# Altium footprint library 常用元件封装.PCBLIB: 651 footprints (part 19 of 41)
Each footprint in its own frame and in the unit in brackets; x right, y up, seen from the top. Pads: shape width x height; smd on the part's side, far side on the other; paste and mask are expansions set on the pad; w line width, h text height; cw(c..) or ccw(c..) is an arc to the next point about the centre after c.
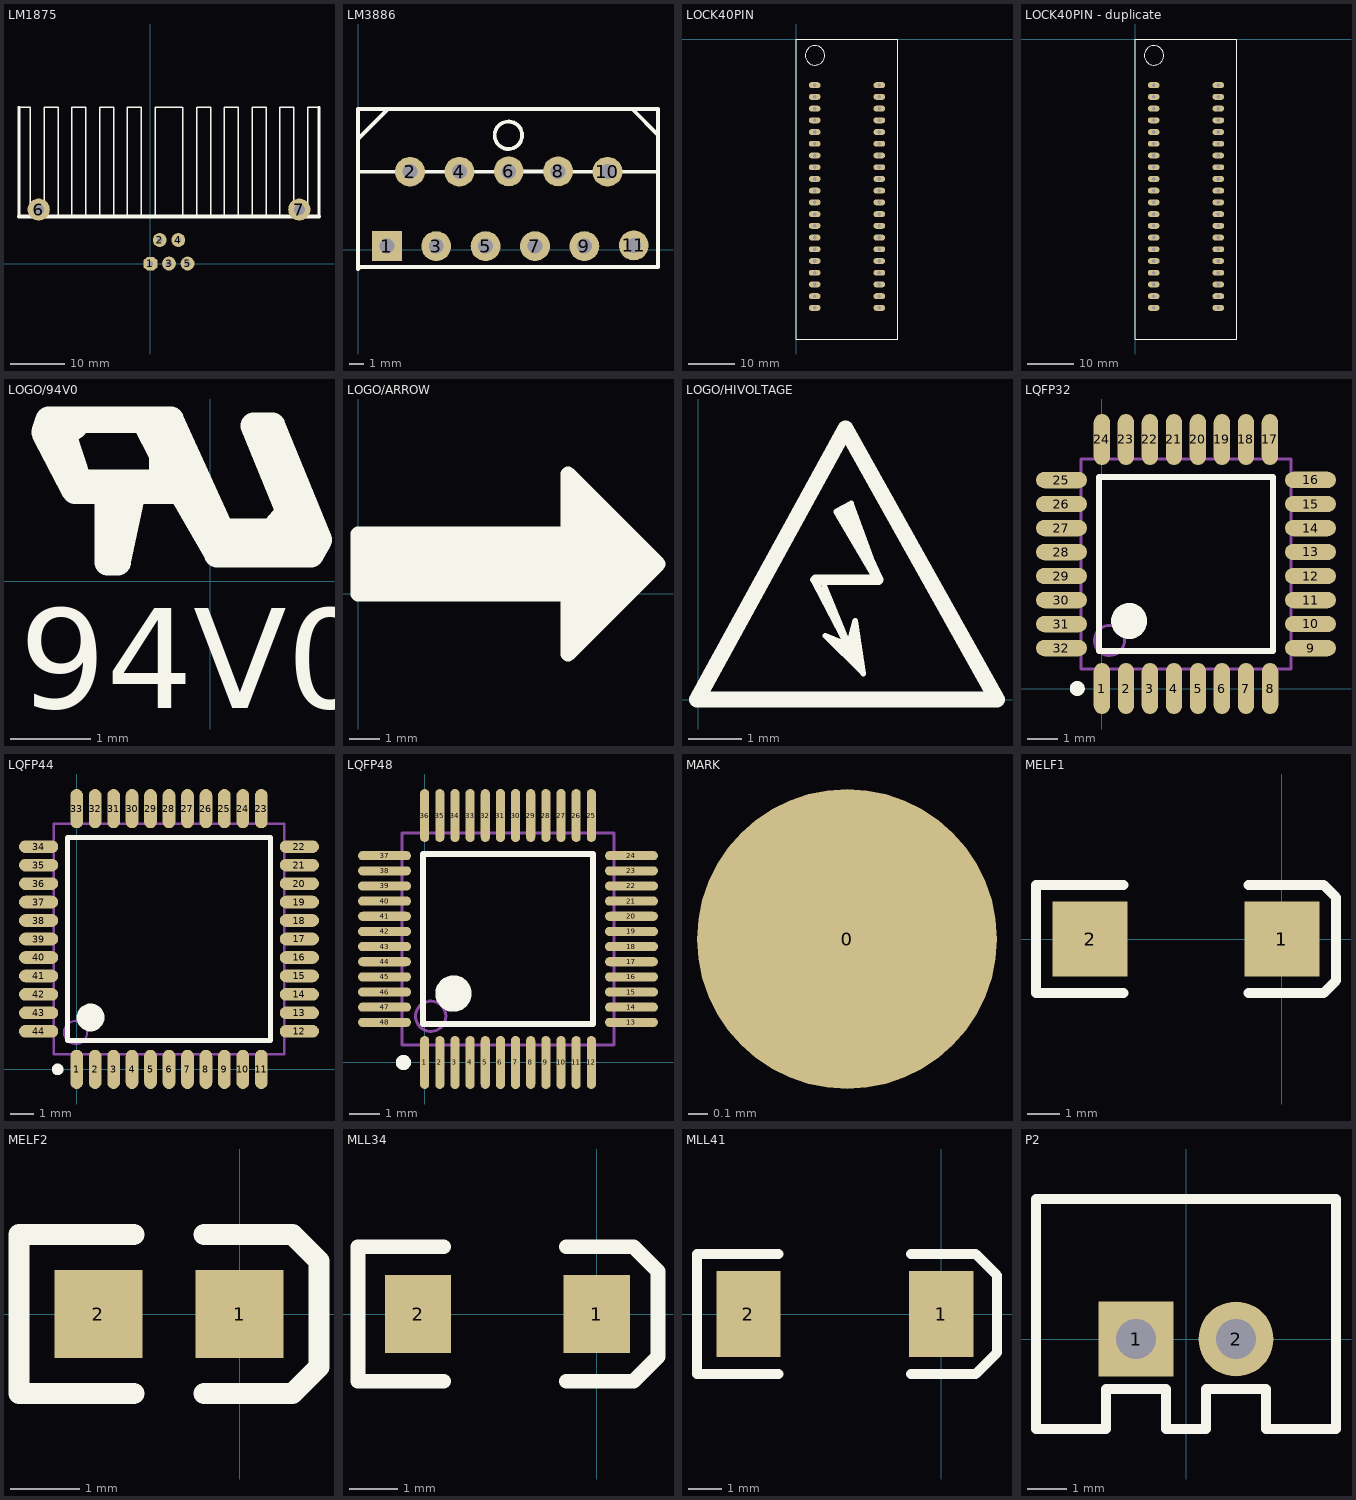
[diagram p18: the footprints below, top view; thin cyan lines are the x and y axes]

## LM1875 [mil]
pads (7):
  oct 100x100 hole 40: 1(0,0)
  round 100 hole 40: 2(67,171) 3(134,1) 4(201,171) 5(268,1)
  round 160 hole 80: 6(-806,391) 7(1074,391)
TopOverlay:
  lines w10: -948,1128 -866,1128 -866,341 ; -766,341 -766,1128 -666,1128 -666,341 ; -566,341 -566,1128 -466,1128 -466,341 ; -366,341 -366,1128 -266,1128 -266,341 ; -166,341 -166,1128 -66,1128 -66,341 ; 34,341 34,1128 229,1128 ; 234,341 234,1128 ; 334,341 334,1128 ; 339,1128 434,1128 434,341 ; 534,341 534,1128 634,1128 ; 934,341 934,1128 1034,1128 1034,341 ; 1134,341 1134,1128 1216,1128 ; 634,1128 634,341 634,1128 ; 734,1128 834,1128 ; 734,1128 734,341 734,1128 ; 834,1128 834,341 834,1128
  lines w20: -948,341 -948,1128 ; 1216,341 1216,1128
  lines w30: -948,341 1216,341

## LM3886 [mm]
pads (11):
  rect 2x2 hole 1: 1(1.93,0.229)
  round 2 hole 1: 2(3.48,5.207) 3(5.232,0.229) 4(6.782,5.207) 5(8.534,0.229) 6(10.084,5.232) 7(11.836,0.229) 8(13.386,5.232) 9(15.138,0.229) 10(16.688,5.207) 11(18.444,0.279)
TopOverlay:
  circle w0.254: c10.058,7.645 r0.918
  lines w0.254: 0,7.315 0,7.391 2.007,9.398 ; 10.846,5.232 13.386,5.232 ; 13.386,4.978 13.386,5.486 ; 16.688,4.978 16.688,5.486 ; 18.237,9.398 18.339,9.398 20.066,7.671 ; 0,5.207 20.066,5.207 ; 0,5.207 0,9.398 20.066,9.398 20.066,5.207 ; 0,5.207 0,-1.295 0.127,-1.168 20.066,-1.168 20.066,5.207

## LOCK40PIN [mm] "green lock IC"
pads (40):
  oval 2.54x1.27 hole 0.8: 1(4,-10) 2(4,-12.54) 3(4,-15.08) 4(4,-17.62) 5(4,-20.16) 6(4,-22.7) 7(4,-25.24) 8(4,-27.78) 9(4,-30.32) 10(4,-32.86) 11(4,-35.4) 12(4,-37.94) 13(4,-40.48) 14(4,-43.02) 15(4,-45.56) 16(4,-48.1) 17(4,-50.64) 18(4,-53.18) 19(4,-55.72) 20(4,-58.26) 21(18,-58.26) 22(18,-55.72) 23(18,-53.18) 24(18,-50.64) 25(18,-48.1) 26(18,-45.56) 27(18,-43.02) 28(18,-40.48) 29(18,-37.94) 30(18,-35.4) 31(18,-32.86) 32(18,-30.32) 33(18,-27.78) 34(18,-25.24) 35(18,-22.7) 36(18,-20.16) 37(18,-17.62) 38(18,-15.08) 39(18,-12.54) 40(18,-10)
TopOverlay:
  circle w0.254: c4.064,-3.556 r2.095
  lines w0.254: 0,-65 0,0 22,0 22,-65 0,-65

## LOCK40PIN - duplicate [mm] "green lock IC"
pads (40):
  oval 2.54x1.27 hole 0.8: 1(4,-10) 2(4,-12.54) 3(4,-15.08) 4(4,-17.62) 5(4,-20.16) 6(4,-22.7) 7(4,-25.24) 8(4,-27.78) 9(4,-30.32) 10(4,-32.86) 11(4,-35.4) 12(4,-37.94) 13(4,-40.48) 14(4,-43.02) 15(4,-45.56) 16(4,-48.1) 17(4,-50.64) 18(4,-53.18) 19(4,-55.72) 20(4,-58.26) 21(18,-58.26) 22(18,-55.72) 23(18,-53.18) 24(18,-50.64) 25(18,-48.1) 26(18,-45.56) 27(18,-43.02) 28(18,-40.48) 29(18,-37.94) 30(18,-35.4) 31(18,-32.86) 32(18,-30.32) 33(18,-27.78) 34(18,-25.24) 35(18,-22.7) 36(18,-20.16) 37(18,-17.62) 38(18,-15.08) 39(18,-12.54) 40(18,-10)
TopOverlay:
  circle w0.254: c4.064,-3.556 r2.095
  lines w0.254: 0,-65 0,0 22,0 22,-65 0,-65

## LOGO/94V0 [mil]
TopOverlay:
  region: 41.5,15.06 41.5,26.48 32.45,26.48 32.45,15.06
  lines w13: -66.4,76.28 -72.4,72.28 -64.4,48.28 -17.4,48.28 ; -50.4,41.28 -50.4,9.28 -45.4,9.28 -37.4,47.28 ; -31.4,77.28 -16.4,48.28 3.6,13.28 49.6,13.28 53.6,20.28 30.6,76.28 21.6,76.28 43.6,22.28 ; -24.4,75.28 -14.4,55.28 ; -23.4,47.28 -23.4,66.28 ; -9.4,44.28 -66.4,44.28 -81.4,73.28 -79.4,79.28 -19.4,79.28 5.6,24.28 30.6,24.28 37.6,32.28
  text "94V0" at -93.93,-62.5 h49.21

## LOGO/ARROW [mil]
TopOverlay:
  lines w19.68: 11.81,7.87 11.81,70.87 ; 287.4,129.92 287.4,-55.12 377.95,35.43 295.28,118.11 ; 299.21,-23.62 362.2,39.37 ; 303.15,-23.62 303.15,110.24 ; 303.15,98.42 326.77,74.8 ; 350.39,43.31 358.27,43.31 ; 0,0 275.59,0 275.59,-78.74 354.33,0 393.7,39.37 354.33,78.74 275.59,157.48 275.59,78.74 0,78.74 0,0
  lines w78.74: 39.37,39.37 314.96,39.37

## LOGO/HIVOLTAGE [mil]
TopOverlay:
  lines w3.94: 84,88 111,36 ; 86,88 112,36 91,87 ; 103,41 116,28 ; 104,137 109,126 ; 112,44 115,36 ; 114,35 115,31 ; 114,48 118,24 ; 130,88 101,138 112,144 132,89 ; 93,47 121,19 115,58 110,40 93,47
  lines w7.87: 86,88 132,88 108,139
  lines w11.81: -1,0 219,0 108,199 -1,0

## LQFP32 [mm] "LQFP32  9.2x9.2mm (max), Pitch 0.80mm"
height 1.6
pads (32):
  oval 0.55x1.7 smd: 1(0,0) 2(0.8,0) 3(1.6,0) 4(2.4,0) 5(3.2,0) 6(4,0) 7(4.8,0) 8(5.6,0) 17(5.6,8.3) 18(4.8,8.3) 19(4,8.3) 20(3.2,8.3) 21(2.4,8.3) 22(1.6,8.3) 23(0.8,8.3) 24(0,8.3)
  oval 1.7x0.55 smd: 9(6.95,1.35) 10(6.95,2.15) 11(6.95,2.95) 12(6.95,3.75) 13(6.95,4.55) 14(6.95,5.35) 15(6.95,6.15) 16(6.95,6.95) 25(-1.35,6.95) 26(-1.35,6.15) 27(-1.35,5.35) 28(-1.35,4.55) 29(-1.35,3.75) 30(-1.35,2.95) 31(-1.35,2.15) 32(-1.35,1.35)
TopOverlay:
  circle w0.6: c0.9,2.25 r0.3
  circle w0.25: c-0.825,0 r0.125
  lines w0.2: -0.1,1.25 -0.1,7.05 5.7,7.05 5.7,1.25 -0.1,1.25
Mechanical13:
  circle w0.1: c0.25,1.6 r0.5
  lines w0.1: -0.7,0.65 -0.7,7.65 6.3,7.65 6.3,0.65 -0.7,0.65

## LQFP44 [mm]
height 1.6
pads (44):
  oval 0.55x1.7 smd: 1(0,0) 2(0.8,0) 3(1.6,0) 4(2.4,0) 5(3.2,0) 6(4,0) 7(4.8,0) 8(5.6,0) 9(6.4,0) 10(7.2,0) 11(8,0) 23(8,11.3) 24(7.2,11.3) 25(6.4,11.3) 26(5.6,11.3) 27(4.8,11.3) 28(4,11.3) 29(3.2,11.3) 30(2.4,11.3) 31(1.6,11.3) 32(0.8,11.3) 33(0,11.3)
  oval 1.7x0.55 smd: 12(9.65,1.65) 13(9.65,2.45) 14(9.65,3.25) 15(9.65,4.05) 16(9.65,4.85) 17(9.65,5.65) 18(9.65,6.45) 19(9.65,7.25) 20(9.65,8.05) 21(9.65,8.85) 22(9.65,9.65) 34(-1.65,9.65) 35(-1.65,8.85) 36(-1.65,8.05) 37(-1.65,7.25) 38(-1.65,6.45) 39(-1.65,5.65) 40(-1.65,4.85) 41(-1.65,4.05) 42(-1.65,3.25) 43(-1.65,2.45) 44(-1.65,1.65)
TopOverlay:
  circle w0.25: c-0.825,0 r0.125
  circle w0.6: c0.6,2.25 r0.3
  lines w0.2: -0.4,1.25 8.4,1.25 8.4,10.05 -0.4,10.05 -0.4,1.25
Mechanical13:
  circle w0.1: c-0.05,1.6 r0.5
  lines w0.1: -1,0.65 9,0.65 9,10.65 -1,10.65 -1,0.65

## LQFP48 [mm]
height 1.6
pads (48):
  oval 0.3x1.75 smd: 1(0,0) 2(0.5,0) 3(1,0) 4(1.5,0) 5(2,0) 6(2.5,0) 7(3,0) 8(3.5,0) 9(4,0) 10(4.5,0) 11(5,0) 12(5.5,0) 25(5.5,8.15) 26(5,8.15) 27(4.5,8.15) 28(4,8.15) 29(3.5,8.15) 30(3,8.15) 31(2.5,8.15) 32(2,8.15) 33(1.5,8.15) 34(1,8.15) 35(0.5,8.15) 36(0,8.15)
  oval 1.75x0.3 smd: 13(6.825,1.325) 14(6.825,1.825) 15(6.825,2.325) 16(6.825,2.825) 17(6.825,3.325) 18(6.825,3.825) 19(6.825,4.325) 20(6.825,4.825) 21(6.825,5.325) 22(6.825,5.825) 23(6.825,6.325) 24(6.825,6.825) 37(-1.325,6.825) 38(-1.325,6.325) 39(-1.325,5.825) 40(-1.325,5.325) 41(-1.325,4.825) 42(-1.325,4.325) 43(-1.325,3.825) 44(-1.325,3.325) 45(-1.325,2.825) 46(-1.325,2.325) 47(-1.325,1.825) 48(-1.325,1.325)
TopOverlay:
  circle w0.25: c-0.7,0 r0.125
  circle w0.6: c0.95,2.275 r0.3
  lines w0.2: -0.05,1.275 5.55,1.275 5.55,6.875 -0.05,6.875 -0.05,1.275
Mechanical13:
  circle w0.1: c0.2,1.525 r0.5
  lines w0.1: -0.75,0.575 6.25,0.575 6.25,7.575 -0.75,7.575 -0.75,0.575

## MARK [mil]
pads (1):
  round 60 all layers, no hole: 0(50000,50000)

## MELF1 [mil]
pads (2):
  rect 90x90 smd: 1(0,0) 2(-230,0)
TopOverlay:
  lines w12: -190,-65 -295,-65 -295,65 -190,65 ; -40,-65 50,-65 65,-50 65,50 50,65 -40,65

## MELF2 [mil]
pads (2):
  rect 50x50 smd: 1(0,0) 2(-80,0)
TopOverlay:
  lines w12: -60,-45 -125,-45 -125,45 -60,45 ; -20,-45 30,-45 45,-30 45,30 30,45 -20,45

## MLL34 [mil]
pads (2):
  rect 54x64 smd: 1(0,0) 2(-146,0)
TopOverlay:
  lines w12: -125,-55 -195,-55 -195,55 -125,55 ; -25,-55 30,-55 50,-35 50,35 30,55 -25,55

## MLL41 [mil]
pads (2):
  rect 75x100 smd: 1(0,0) 2(-225,0)
TopOverlay:
  lines w12: -190,-70 -285,-70 -285,70 -190,70 ; -35,-70 40,-70 65,-45 65,45 40,70 -35,70

## P2 [mil]
pads (2):
  rect 75x75 hole 40: 1(-50,0)
  round 75 hole 40: 2(50,0)
TopOverlay:
  lines w10: -150,-90 -150,140 150,140 150,-90 80,-90 80,-50 20,-50 20,-90 -20,-90 -20,-50 -80,-50 -80,-90 -150,-90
